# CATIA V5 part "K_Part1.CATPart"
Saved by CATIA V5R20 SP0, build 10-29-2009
Part number: glissiere_roue_droite
Publications: "Corps principal", "largeur de la glissière", "Ecart entre les barres du corps", "Longueur de barres du corps", "Point.1", "Point.2", "Point.3", "Point.4", "Droite.1", "Droite.2", "Droite.3", "Droite.4", "Droite.5"
Bounding box of the stored display mesh (mm): x -50 to 50, y -500 to -400, z 0 to 0
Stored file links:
  G:\Khaled_CFAO_2011\ST2M\ST2M_GR1\cdurantin\cdurantin\Khaled\CAD_ThinkMOTION\K_Part1.CATPart
  G:\Khaled_CFAO_2011\ST2M\ST2M_GR1\cdurantin\cdurantin\Khaled\CAD_ThinkMOTION\K_Part4.CATPart
  G:\Khaled_CFAO_2011\ST2M\ST2M_GR1\cdurantin\cdurantin\Khaled\CAD_ThinkMOTION\K_Corps.CATPart
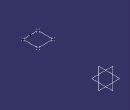
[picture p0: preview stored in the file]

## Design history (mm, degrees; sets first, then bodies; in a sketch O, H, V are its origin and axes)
External parameters (linked from other documents)
  `External.largeur de la glissière` = 100 mm
  `External.Ecart entre les barres du corps` = 100 mm
  `External.Longueur de barres du corps` = 800 mm
Body1 (main body)
  Point1: type OnPlane, Support xy-plane, H 50 {= `External.Ecart entre les barres du corps` /2}, V -400 {= -`External.Longueur de barres du corps` /2}, Direction (1, 0, 0)
  Point2: type OnPlane, Support xy-plane, H -50 {= -`External.Ecart entre les barres du corps` /2}, V -400 {= -`External.Longueur de barres du corps` /2}, Direction (1, 0, 0)
  Point3: type OnPlane, Support xy-plane, H 50 {= `External.Ecart entre les barres du corps` /2}, V -500 {= -`External.Longueur de barres du corps` /2-`External.largeur de la glissière`}, Direction (1, 0, 0)
  Point4: type OnPlane, Support xy-plane, H -50 {= -`External.Ecart entre les barres du corps` /2}, V -500 {= -`External.Longueur de barres du corps` /2-`External.largeur de la glissière`}, Direction (1, 0, 0)
  Line1: type PtPt, FirstPoint Point2, SecondPoint Point1
  Line2: type PtPt, FirstPoint Point1, SecondPoint Point3
  Line3: type PtPt, FirstPoint Point2, SecondPoint Point4
  Line4: type PtDir, RefPoint Point4, Direction yz-plane, Start 0, End 50
  Line5: type PtDir, RefPoint Point3, Direction yz-plane, Start 0, End -50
